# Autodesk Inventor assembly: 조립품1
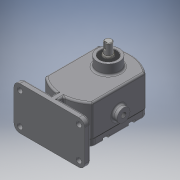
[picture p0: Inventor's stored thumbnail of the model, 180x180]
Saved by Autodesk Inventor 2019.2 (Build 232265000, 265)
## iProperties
Created: 2019-03
Part Number: 조립품1
Material: 일반
Document SubType Name: Assembly
Designer: User
Author: User
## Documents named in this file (11)
- C:\Users\User\Desktop\490307V1033\조립품1.iam
- C:\Users\User\Desktop\490307V1033\본체.ipt
- C:\Users\User\Desktop\490307V1033\메인축.ipt
- C:\Users\User\Desktop\490307V1033\오일 실 16 28 7.ipt
- C:\Users\User\Desktop\490307V1033\베어링부시.ipt
- C:\Users\User\Desktop\490307V1033\서브축.ipt
- C:\Users\User\Desktop\490307V1033\키 6 x 6 x 18.ipt
- C:\Users\User\Desktop\490307V1033\스퍼기어.ipt
- C:\Users\User\Desktop\490307V1033\커버.ipt
- C:\Users\User\Desktop\490307V1033\개스킷.ipt
- C:\Users\User\Desktop\490307V1033\볼트 M5.ipt
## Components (1 placed, 1 different names)
1. 개스킷:1
